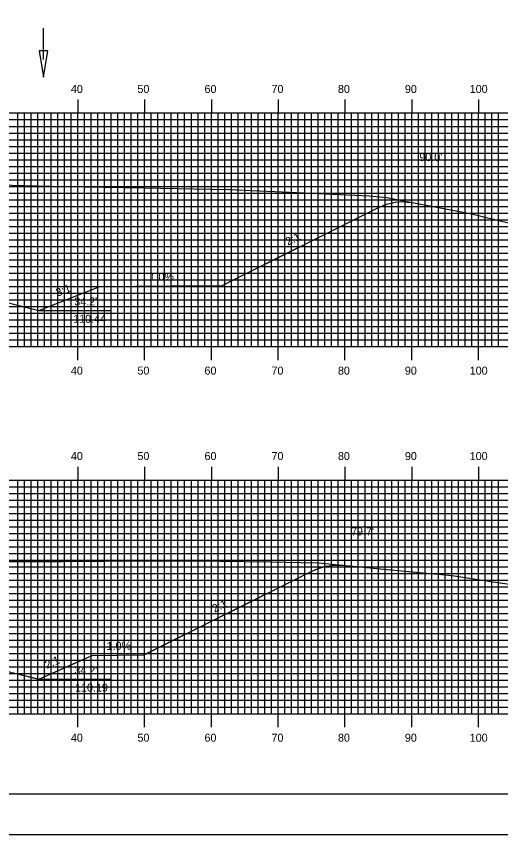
# Model space of a CAD drawing. Extents: x 1767300 to 1767643, y 442591 to 442811.
# Drawn here: x 1767496.7 to 1767569.2, y 442590.5 to 442713.1 of the extents above; entities that cross this region are included whole.
import ezdxf

# ---------------------------------------------------------------- set-up
doc = ezdxf.new("R2010")
doc.units = 0
for name, color, linetype in [('ANNOTATION', 7, 'Continuous'), ('BORDER', 7, 'Continuous'), ('D_Drainage_Ditch_Line', 7, 'Continuous'), ('D_Roadway_Centerline', 7, 'Continuous'), ('D_Roadway_SlopeLines', 7, 'Continuous'), ('D_Text_Standard', 7, 'Continuous'), ('H_V ANNOTATION', 7, 'Continuous'), ('MAJOR', 7, 'Continuous'), ('MINOR', 7, 'Continuous'), ('PDRAIN', 7, 'Continuous'), ('PLOT BOUNDARY', 7, 'Continuous'), ('S_Roadway_Centerline', 7, 'Continuous')]:
    doc.layers.add(name, color=color, linetype=linetype)

msp = doc.modelspace()

# ---------------------------------------------------------------- linework, layer by layer
at = {"layer": 'BORDER'}
msp.add_lwpolyline([(1767316.34, 442596.67), (1767636.34, 442596.67), (1767636.34, 442806.67), (1767316.34, 442806.67)], close=True, dxfattribs=at)
at = {"layer": 'D_Drainage_Ditch_Line'}
msp.add_line((1767500.8, 442706.66), (1767500.8, 442711.36), dxfattribs=at)
msp.add_lwpolyline([(1767501.46, 442707.97), (1767500.14, 442707.97), (1767500.8, 442704.03)], close=True, dxfattribs=at)
at = {"layer": 'D_Roadway_Centerline'}
for points in [[(1767496.11, 442670.1), (1767500.11, 442669.1), (1767509.22, 442672.65), (1767509.22, 442672.65), (1767520.02, 442672.75), (1767527.56, 442672.83), (1767527.57, 442672.83), (1767540.07, 442679.08), (1767550.94, 442684.52), (1767551.33, 442684.68), (1767552.19, 442685.03), (1767553.44, 442685.33), (1767554.69, 442685.4), (1767555.32, 442685.33), (1767555.94, 442685.26)], [(1767496.11, 442614.85), (1767498.75, 442614.19), (1767500.11, 442613.85), (1767506.13, 442616.53), (1767508.08, 442617.4), (1767515.85, 442617.47), (1767515.86, 442617.48), (1767540.69, 442629.89), (1767541.94, 442630.42), (1767543.19, 442630.77), (1767543.6, 442630.82), (1767544.44, 442630.93), (1767544.86, 442630.92), (1767545.69, 442630.9)]]:
    msp.add_lwpolyline(points, dxfattribs=at)
at = {"layer": 'D_Roadway_SlopeLines'}
for points in [[(1767509.22, 442672.65), (1767527.56, 442672.83), (1767550.94, 442684.52), (1767552.19, 442685.03), (1767553.44, 442685.33), (1767554.69, 442685.4), (1767555.94, 442685.26)], [(1767485.94, 442672.65), (1767500.11, 442669.1)], [(1767500.11, 442669.1), (1767509.22, 442672.65)], [(1767508.08, 442617.4), (1767515.85, 442617.47), (1767540.69, 442629.89), (1767541.94, 442630.42), (1767543.19, 442630.77), (1767544.44, 442630.93), (1767545.69, 442630.9)], [(1767485.94, 442617.4), (1767500.11, 442613.85)], [(1767500.11, 442613.85), (1767508.08, 442617.4)]]:
    msp.add_lwpolyline(points, dxfattribs=at)
at = {"layer": 'MAJOR'}
for p, q in [((1767505.94, 442700.67), (1767505.94, 442698.67)), ((1767515.94, 442700.67), (1767515.94, 442698.67)), ((1767525.94, 442700.67), (1767525.94, 442698.67)), ((1767535.94, 442700.67), (1767535.94, 442698.67)), ((1767545.94, 442700.67), (1767545.94, 442698.67)), ((1767555.94, 442700.67), (1767555.94, 442698.67)), ((1767565.94, 442700.67), (1767565.94, 442698.67)), ((1767325.94, 442698.67), (1767605.94, 442698.67)), ((1767325.94, 442698.67), (1767605.94, 442698.67)), ((1767505.94, 442663.67), (1767505.94, 442698.67)), ((1767515.94, 442663.67), (1767515.94, 442698.67)), ((1767525.94, 442663.67), (1767525.94, 442698.67)), ((1767535.94, 442663.67), (1767535.94, 442698.67)), ((1767545.94, 442663.67), (1767545.94, 442698.67)), ((1767555.94, 442663.67), (1767555.94, 442698.67)), ((1767565.94, 442663.67), (1767565.94, 442698.67)), ((1767325.94, 442693.67), (1767605.94, 442693.67)), ((1767325.94, 442688.67), (1767605.94, 442688.67)), ((1767325.94, 442683.67), (1767605.94, 442683.67)), ((1767325.94, 442678.67), (1767605.94, 442678.67)), ((1767325.94, 442673.67), (1767605.94, 442673.67)), ((1767325.94, 442668.67), (1767605.94, 442668.67)), ((1767325.94, 442663.67), (1767605.94, 442663.67)), ((1767325.94, 442663.67), (1767605.94, 442663.67)), ((1767505.94, 442661.66), (1767505.94, 442663.67)), ((1767515.94, 442661.66), (1767515.94, 442663.67)), ((1767525.94, 442661.66), (1767525.94, 442663.67)), ((1767535.94, 442661.66), (1767535.94, 442663.67)), ((1767545.94, 442661.66), (1767545.94, 442663.67)), ((1767555.94, 442661.66), (1767555.94, 442663.67)), ((1767565.94, 442661.66), (1767565.94, 442663.67)), ((1767505.94, 442645.67), (1767505.94, 442643.67)), ((1767515.94, 442645.67), (1767515.94, 442643.67)), ((1767525.94, 442645.67), (1767525.94, 442643.67)), ((1767535.94, 442645.67), (1767535.94, 442643.67)), ((1767545.94, 442645.67), (1767545.94, 442643.67)), ((1767555.94, 442645.67), (1767555.94, 442643.67)), ((1767565.94, 442645.67), (1767565.94, 442643.67)), ((1767325.94, 442643.67), (1767605.94, 442643.67)), ((1767325.94, 442643.67), (1767605.94, 442643.67)), ((1767505.94, 442608.67), (1767505.94, 442643.67)), ((1767515.94, 442608.67), (1767515.94, 442643.67)), ((1767525.94, 442608.67), (1767525.94, 442643.67)), ((1767535.94, 442608.67), (1767535.94, 442643.67)), ((1767545.94, 442608.67), (1767545.94, 442643.67)), ((1767555.94, 442608.67), (1767555.94, 442643.67)), ((1767565.94, 442608.67), (1767565.94, 442643.67)), ((1767325.94, 442638.67), (1767605.94, 442638.67)), ((1767325.94, 442633.67), (1767605.94, 442633.67)), ((1767325.94, 442628.67), (1767605.94, 442628.67)), ((1767325.94, 442623.67), (1767605.94, 442623.67)), ((1767325.94, 442618.67), (1767605.94, 442618.67)), ((1767325.94, 442613.67), (1767605.94, 442613.67)), ((1767325.94, 442608.67), (1767605.94, 442608.67)), ((1767325.94, 442608.67), (1767605.94, 442608.67)), ((1767505.94, 442606.66), (1767505.94, 442608.67)), ((1767515.94, 442606.66), (1767515.94, 442608.67)), ((1767525.94, 442606.66), (1767525.94, 442608.67)), ((1767535.94, 442606.66), (1767535.94, 442608.67)), ((1767545.94, 442606.66), (1767545.94, 442608.67)), ((1767555.94, 442606.66), (1767555.94, 442608.67)), ((1767565.94, 442606.66), (1767565.94, 442608.67))]:
    msp.add_line(p, q, dxfattribs=at)
at = {"layer": 'MINOR'}
for p, q in [((1767496.94, 442663.67), (1767496.94, 442698.67)), ((1767497.94, 442663.67), (1767497.94, 442698.67)), ((1767498.94, 442663.67), (1767498.94, 442698.67)), ((1767499.94, 442663.67), (1767499.94, 442698.67)), ((1767500.94, 442663.67), (1767500.94, 442698.67)), ((1767501.94, 442663.67), (1767501.94, 442698.67)), ((1767502.94, 442663.67), (1767502.94, 442698.67)), ((1767503.94, 442663.67), (1767503.94, 442698.67)), ((1767504.94, 442663.67), (1767504.94, 442698.67)), ((1767506.94, 442663.67), (1767506.94, 442698.67)), ((1767507.94, 442663.67), (1767507.94, 442698.67)), ((1767508.94, 442663.67), (1767508.94, 442698.67)), ((1767509.94, 442663.67), (1767509.94, 442698.67)), ((1767510.94, 442663.67), (1767510.94, 442698.67)), ((1767511.94, 442663.67), (1767511.94, 442698.67)), ((1767512.94, 442663.67), (1767512.94, 442698.67)), ((1767513.94, 442663.67), (1767513.94, 442698.67)), ((1767514.94, 442663.67), (1767514.94, 442698.67)), ((1767516.94, 442663.67), (1767516.94, 442698.67)), ((1767517.94, 442663.67), (1767517.94, 442698.67)), ((1767518.94, 442663.67), (1767518.94, 442698.67)), ((1767519.94, 442663.67), (1767519.94, 442698.67)), ((1767520.94, 442663.67), (1767520.94, 442698.67)), ((1767521.94, 442663.67), (1767521.94, 442698.67)), ((1767522.94, 442663.67), (1767522.94, 442698.67)), ((1767523.94, 442663.67), (1767523.94, 442698.67)), ((1767524.94, 442663.67), (1767524.94, 442698.67)), ((1767526.94, 442663.67), (1767526.94, 442698.67)), ((1767527.94, 442663.67), (1767527.94, 442698.67)), ((1767528.94, 442663.67), (1767528.94, 442698.67)), ((1767529.94, 442663.67), (1767529.94, 442698.67)), ((1767530.94, 442663.67), (1767530.94, 442698.67)), ((1767531.94, 442663.67), (1767531.94, 442698.67)), ((1767532.94, 442663.67), (1767532.94, 442698.67)), ((1767533.94, 442663.67), (1767533.94, 442698.67)), ((1767534.94, 442663.67), (1767534.94, 442698.67)), ((1767536.94, 442663.67), (1767536.94, 442698.67)), ((1767537.94, 442663.67), (1767537.94, 442698.67)), ((1767538.94, 442663.67), (1767538.94, 442698.67)), ((1767539.94, 442663.67), (1767539.94, 442698.67)), ((1767540.94, 442663.67), (1767540.94, 442698.67)), ((1767541.94, 442663.67), (1767541.94, 442698.67)), ((1767542.94, 442663.67), (1767542.94, 442698.67)), ((1767543.94, 442663.67), (1767543.94, 442698.67)), ((1767544.94, 442663.67), (1767544.94, 442698.67)), ((1767546.94, 442663.67), (1767546.94, 442698.67)), ((1767547.94, 442663.67), (1767547.94, 442698.67)), ((1767548.94, 442663.67), (1767548.94, 442698.67)), ((1767549.94, 442663.67), (1767549.94, 442698.67)), ((1767550.94, 442663.67), (1767550.94, 442698.67)), ((1767551.94, 442663.67), (1767551.94, 442698.67)), ((1767552.94, 442663.67), (1767552.94, 442698.67)), ((1767553.94, 442663.67), (1767553.94, 442698.67)), ((1767554.94, 442663.67), (1767554.94, 442698.67)), ((1767556.94, 442663.67), (1767556.94, 442698.67)), ((1767557.94, 442663.67), (1767557.94, 442698.67)), ((1767558.94, 442663.67), (1767558.94, 442698.67)), ((1767559.94, 442663.67), (1767559.94, 442698.67)), ((1767560.94, 442663.67), (1767560.94, 442698.67)), ((1767561.94, 442663.67), (1767561.94, 442698.67)), ((1767562.94, 442663.67), (1767562.94, 442698.67)), ((1767563.94, 442663.67), (1767563.94, 442698.67)), ((1767564.94, 442663.67), (1767564.94, 442698.67)), ((1767566.94, 442663.67), (1767566.94, 442698.67)), ((1767567.94, 442663.67), (1767567.94, 442698.67)), ((1767568.94, 442663.67), (1767568.94, 442698.67)), ((1767325.94, 442697.67), (1767605.94, 442697.67)), ((1767325.94, 442696.67), (1767605.94, 442696.67)), ((1767325.94, 442695.67), (1767605.94, 442695.67)), ((1767325.94, 442694.67), (1767605.94, 442694.67)), ((1767325.94, 442692.67), (1767605.94, 442692.67)), ((1767325.94, 442691.67), (1767605.94, 442691.67)), ((1767325.94, 442690.67), (1767605.94, 442690.67)), ((1767325.94, 442689.67), (1767605.94, 442689.67)), ((1767325.94, 442687.67), (1767605.94, 442687.67)), ((1767325.94, 442686.67), (1767605.94, 442686.67)), ((1767325.94, 442685.67), (1767605.94, 442685.67)), ((1767325.94, 442684.67), (1767605.94, 442684.67)), ((1767325.94, 442682.67), (1767605.94, 442682.67)), ((1767325.94, 442681.67), (1767605.94, 442681.67)), ((1767325.94, 442680.67), (1767605.94, 442680.67)), ((1767325.94, 442679.67), (1767605.94, 442679.67)), ((1767325.94, 442677.67), (1767605.94, 442677.67)), ((1767325.94, 442676.67), (1767605.94, 442676.67)), ((1767325.94, 442675.67), (1767605.94, 442675.67)), ((1767325.94, 442674.67), (1767605.94, 442674.67)), ((1767325.94, 442672.67), (1767605.94, 442672.67)), ((1767325.94, 442671.67), (1767605.94, 442671.67)), ((1767325.94, 442670.67), (1767605.94, 442670.67)), ((1767325.94, 442669.67), (1767605.94, 442669.67)), ((1767325.94, 442667.67), (1767605.94, 442667.67)), ((1767325.94, 442666.67), (1767605.94, 442666.67)), ((1767325.94, 442665.67), (1767605.94, 442665.67)), ((1767325.94, 442664.67), (1767605.94, 442664.67)), ((1767496.94, 442608.67), (1767496.94, 442643.67)), ((1767497.94, 442608.67), (1767497.94, 442643.67)), ((1767498.94, 442608.67), (1767498.94, 442643.67)), ((1767499.94, 442608.67), (1767499.94, 442643.67)), ((1767500.94, 442608.67), (1767500.94, 442643.67)), ((1767501.94, 442608.67), (1767501.94, 442643.67)), ((1767502.94, 442608.67), (1767502.94, 442643.67)), ((1767503.94, 442608.67), (1767503.94, 442643.67)), ((1767504.94, 442608.67), (1767504.94, 442643.67)), ((1767506.94, 442608.67), (1767506.94, 442643.67)), ((1767507.94, 442608.67), (1767507.94, 442643.67)), ((1767508.94, 442608.67), (1767508.94, 442643.67)), ((1767509.94, 442608.67), (1767509.94, 442643.67)), ((1767510.94, 442608.67), (1767510.94, 442643.67)), ((1767511.94, 442608.67), (1767511.94, 442643.67)), ((1767512.94, 442608.67), (1767512.94, 442643.67)), ((1767513.94, 442608.67), (1767513.94, 442643.67)), ((1767514.94, 442608.67), (1767514.94, 442643.67)), ((1767516.94, 442608.67), (1767516.94, 442643.67)), ((1767517.94, 442608.67), (1767517.94, 442643.67)), ((1767518.94, 442608.67), (1767518.94, 442643.67)), ((1767519.94, 442608.67), (1767519.94, 442643.67)), ((1767520.94, 442608.67), (1767520.94, 442643.67)), ((1767521.94, 442608.67), (1767521.94, 442643.67)), ((1767522.94, 442608.67), (1767522.94, 442643.67)), ((1767523.94, 442608.67), (1767523.94, 442643.67)), ((1767524.94, 442608.67), (1767524.94, 442643.67)), ((1767526.94, 442608.67), (1767526.94, 442643.67)), ((1767527.94, 442608.67), (1767527.94, 442643.67)), ((1767528.94, 442608.67), (1767528.94, 442643.67)), ((1767529.94, 442608.67), (1767529.94, 442643.67)), ((1767530.94, 442608.67), (1767530.94, 442643.67)), ((1767531.94, 442608.67), (1767531.94, 442643.67)), ((1767532.94, 442608.67), (1767532.94, 442643.67)), ((1767533.94, 442608.67), (1767533.94, 442643.67)), ((1767534.94, 442608.67), (1767534.94, 442643.67)), ((1767536.94, 442608.67), (1767536.94, 442643.67)), ((1767537.94, 442608.67), (1767537.94, 442643.67)), ((1767538.94, 442608.67), (1767538.94, 442643.67)), ((1767539.94, 442608.67), (1767539.94, 442643.67)), ((1767540.94, 442608.67), (1767540.94, 442643.67)), ((1767541.94, 442608.67), (1767541.94, 442643.67)), ((1767542.94, 442608.67), (1767542.94, 442643.67)), ((1767543.94, 442608.67), (1767543.94, 442643.67)), ((1767544.94, 442608.67), (1767544.94, 442643.67)), ((1767546.94, 442608.67), (1767546.94, 442643.67)), ((1767547.94, 442608.67), (1767547.94, 442643.67)), ((1767548.94, 442608.67), (1767548.94, 442643.67)), ((1767549.94, 442608.67), (1767549.94, 442643.67)), ((1767550.94, 442608.67), (1767550.94, 442643.67)), ((1767551.94, 442608.67), (1767551.94, 442643.67)), ((1767552.94, 442608.67), (1767552.94, 442643.67)), ((1767553.94, 442608.67), (1767553.94, 442643.67)), ((1767554.94, 442608.67), (1767554.94, 442643.67)), ((1767556.94, 442608.67), (1767556.94, 442643.67)), ((1767557.94, 442608.67), (1767557.94, 442643.67)), ((1767558.94, 442608.67), (1767558.94, 442643.67)), ((1767559.94, 442608.67), (1767559.94, 442643.67)), ((1767560.94, 442608.67), (1767560.94, 442643.67)), ((1767561.94, 442608.67), (1767561.94, 442643.67)), ((1767562.94, 442608.67), (1767562.94, 442643.67)), ((1767563.94, 442608.67), (1767563.94, 442643.67)), ((1767564.94, 442608.67), (1767564.94, 442643.67)), ((1767566.94, 442608.67), (1767566.94, 442643.67)), ((1767567.94, 442608.67), (1767567.94, 442643.67)), ((1767568.94, 442608.67), (1767568.94, 442643.67)), ((1767325.94, 442642.67), (1767605.94, 442642.67)), ((1767325.94, 442641.67), (1767605.94, 442641.67)), ((1767325.94, 442640.67), (1767605.94, 442640.67)), ((1767325.94, 442639.67), (1767605.94, 442639.67)), ((1767325.94, 442637.67), (1767605.94, 442637.67)), ((1767325.94, 442636.67), (1767605.94, 442636.67)), ((1767325.94, 442635.67), (1767605.94, 442635.67)), ((1767325.94, 442634.67), (1767605.94, 442634.67)), ((1767325.94, 442632.67), (1767605.94, 442632.67)), ((1767325.94, 442631.67), (1767605.94, 442631.67)), ((1767325.94, 442630.67), (1767605.94, 442630.67)), ((1767325.94, 442629.67), (1767605.94, 442629.67)), ((1767325.94, 442627.67), (1767605.94, 442627.67)), ((1767325.94, 442626.67), (1767605.94, 442626.67)), ((1767325.94, 442625.67), (1767605.94, 442625.67)), ((1767325.94, 442624.67), (1767605.94, 442624.67)), ((1767325.94, 442622.67), (1767605.94, 442622.67)), ((1767325.94, 442621.67), (1767605.94, 442621.67)), ((1767325.94, 442620.67), (1767605.94, 442620.67)), ((1767325.94, 442619.67), (1767605.94, 442619.67)), ((1767325.94, 442617.67), (1767605.94, 442617.67)), ((1767325.94, 442616.67), (1767605.94, 442616.67)), ((1767325.94, 442615.67), (1767605.94, 442615.67)), ((1767325.94, 442614.67), (1767605.94, 442614.67)), ((1767325.94, 442612.67), (1767605.94, 442612.67)), ((1767325.94, 442611.67), (1767605.94, 442611.67)), ((1767325.94, 442610.67), (1767605.94, 442610.67)), ((1767325.94, 442609.67), (1767605.94, 442609.67))]:
    msp.add_line(p, q, dxfattribs=at)
at = {"layer": 'PDRAIN'}
for p, q in [((1767500.11, 442669.1), (1767510.88, 442669.1)), ((1767500.11, 442613.85), (1767510.88, 442613.85))]:
    msp.add_line(p, q, dxfattribs=at)
at = {"layer": 'PLOT BOUNDARY'}
msp.add_lwpolyline([(1767300.15, 442590.55), (1767640.15, 442590.55), (1767640.15, 442810.55), (1767300.15, 442810.55)], close=True, dxfattribs=at)
at = {"layer": 'S_Roadway_Centerline'}
for points in [[(1767492.19, 442687.95), (1767503.68, 442687.68), (1767503.89, 442687.68), (1767504.02, 442687.68), (1767515.87, 442687.45), (1767523.31, 442687.33), (1767528.58, 442687.2), (1767535.45, 442686.9), (1767549.54, 442686.24), (1767552.23, 442686.02), (1767555.19, 442685.4), (1767564.66, 442683.6), (1767570.63, 442682.14), (1767584.43, 442679.45), (1767588.56, 442678.95), (1767599.71, 442679.05), (1767605.94, 442678.92)], [(1767484.67, 442631.49), (1767502.67, 442631.45), (1767503.67, 442631.45), (1767515.91, 442631.58), (1767523.45, 442631.58), (1767534.8, 442631.42), (1767539.36, 442631.33), (1767541.96, 442631.26), (1767552.26, 442630.26), (1767562.01, 442629.38), (1767568.14, 442628.43), (1767575.79, 442627.34), (1767581.25, 442626.23), (1767597.6, 442623.32), (1767599.97, 442623), (1767605.94, 442623.06)]]:
    msp.add_lwpolyline(points, dxfattribs=at)

# ---------------------------------------------------------------- texts
at = {"layer": 'ANNOTATION'}
for s, rotation, p in [('2:1', 26.5653, (1767537.4, 442678.78)), ('1.0%', 0.5717, (1767516.68, 442673.52)), ('3:1', 21.2538, (1767502.93, 442671.14)), ('2:1', 26.565, (1767526.42, 442623.79)), ('1.0%', 0.5679, (1767510.26, 442618.22)), ('2:1', 23.9642, (1767501.33, 442615.38))]:
    msp.add_text(s, height=1.2, rotation=rotation, dxfattribs=at).set_placement(p)
for s, p in [("34.2'", (1767505.42, 442669.83)), ('110.44', (1767505.25, 442667.23)), ("34.2'", (1767505.42, 442614.58)), ('110.19', (1767505.53, 442611.98))]:
    msp.add_text(s, height=1.2, dxfattribs=at).set_placement(p)
at = {"layer": 'D_Text_Standard'}
for s, p in [("90.0'", (1767557.08, 442691.46)), ("79.7'", (1767546.86, 442635.38))]:
    msp.add_text(s, height=1.2, dxfattribs=at).set_placement(p)
at = {"layer": 'H_V ANNOTATION'}
for s, p in [('40', (1767504.91, 442701.67)), ('50', (1767514.87, 442701.67)), ('60', (1767524.91, 442701.67)), ('70', (1767534.94, 442701.67)), ('80', (1767544.89, 442701.67)), ('90', (1767554.91, 442701.67)), ('100', (1767564.62, 442701.67)), ('40', (1767504.91, 442659.47)), ('50', (1767514.87, 442659.47)), ('60', (1767524.91, 442659.47)), ('70', (1767534.94, 442659.47)), ('80', (1767544.89, 442659.47)), ('90', (1767554.91, 442659.47)), ('100', (1767564.62, 442659.47)), ('40', (1767504.91, 442646.67)), ('50', (1767514.87, 442646.67)), ('60', (1767524.91, 442646.67)), ('70', (1767534.94, 442646.67)), ('80', (1767544.89, 442646.67)), ('90', (1767554.91, 442646.67)), ('100', (1767564.62, 442646.67)), ('40', (1767504.91, 442604.47)), ('50', (1767514.87, 442604.47)), ('60', (1767524.91, 442604.47)), ('70', (1767534.94, 442604.47)), ('80', (1767544.89, 442604.47)), ('90', (1767554.91, 442604.47)), ('100', (1767564.62, 442604.47))]:
    msp.add_text(s, height=1.2, dxfattribs=at).set_placement(p)

doc.saveas('drawing.dxf')
